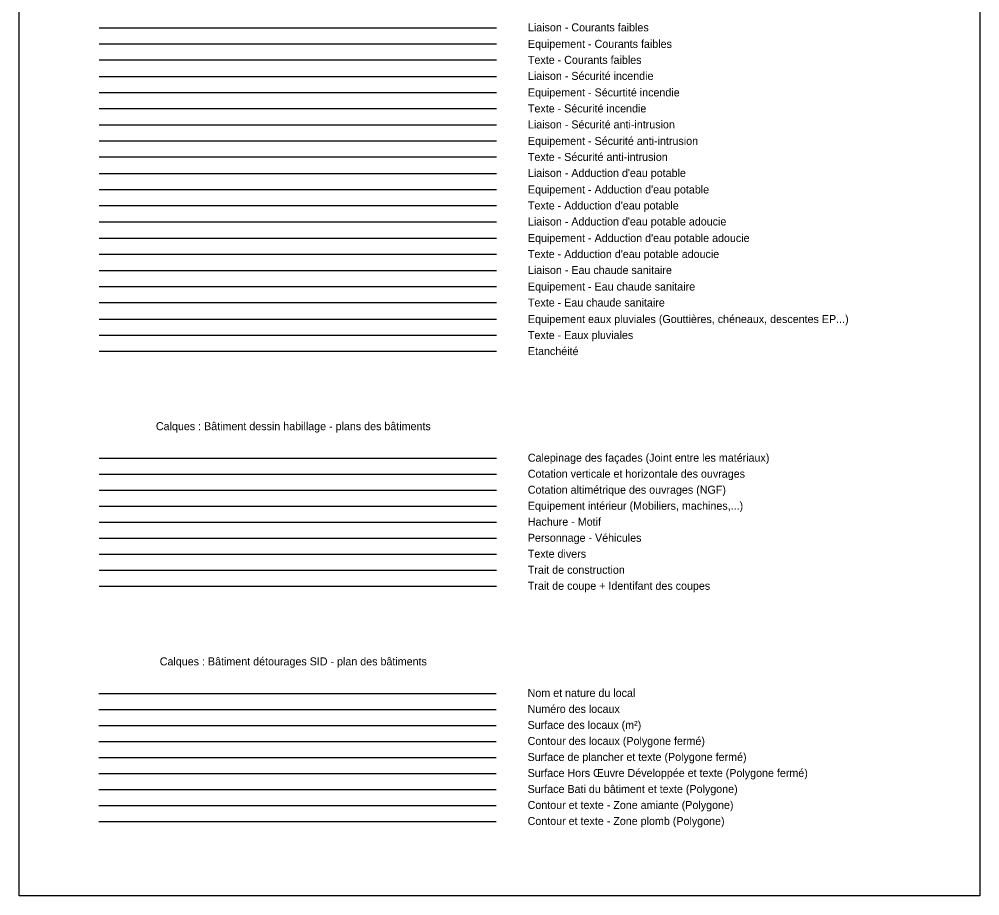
# Model space of a CAD drawing. Extents: x 703432 to 707394, y 7057985 to 7059523.
# Drawn here: x 707334.5 to 707394.5, y 7058534.6 to 7058589.3 of the extents above; entities that cross this region are included whole.
import ezdxf

# ---------------------------------------------------------------- set-up
doc = ezdxf.new("R2010")
doc.units = 0
for name, color, linetype in [('BAT_DH_CALEPINAGE_FACADE', 7, 'Continuous'), ('BAT_DH_COTATION', 7, 'Continuous'), ('BAT_DH_COTATION_NGF', 7, 'Continuous'), ('BAT_DH_EQUIP INTERIEUR', 7, 'Continuous'), ('BAT_DH_HACHURE-MOTIF', 7, 'Continuous'), ('BAT_DH_PERSONNAGE_VEHICULES', 7, 'Continuous'), ('BAT_DH_TEXTE', 7, 'Continuous'), ('BAT_DH_TRAIT CONSTRUCTION', 7, 'Continuous'), ('BAT_DH_TRAIT DE COUPE', 7, 'Continuous'), ('BAT_SID_AMIANTE_POLYLIGNE_TEXTE', 7, 'Continuous'), ('BAT_SID_LOCAL_NOM', 7, 'Continuous'), ('BAT_SID_LOCAL_NUMERO', 7, 'Continuous'), ('BAT_SID_LOCAL_POLYLIGNE', 7, 'Continuous'), ('BAT_SID_LOCAL_SURFACE', 7, 'Continuous'), ('BAT_SID_PLOMB_POLYLIGNE_TEXTE', 7, 'Continuous'), ('BAT_SID_SBAT_POLYLIGNE_TEXTE', 7, 'Continuous'), ('BAT_SID_SDP_POLYLIGNE_TEXTE', 7, 'Continuous'), ('BAT_SID_SHOD _POLYLIGNE_TEXTE', 7, 'Continuous'), ('DH_CADRE -CARTOUCHE', 7, 'Continuous'), ('GO_COUVERTURE', 7, 'Continuous'), ('SO_AEP_AD_EQUIP', 7, 'Continuous'), ('SO_AEP_AD_LIAISON', 7, 'Continuous'), ('SO_AEP_AD_TEXTE', 7, 'Continuous'), ('SO_AEP_EQUIP', 7, 'Continuous'), ('SO_AEP_LIAISON', 7, 'Continuous'), ('SO_AEP_TEXTE', 7, 'Continuous'), ('SO_ANTI_INTRUSION_EQUIP', 7, 'Continuous'), ('SO_ANTI_INTRUSION_LIAISON', 7, 'Continuous'), ('SO_ANTI_INTRUSION_TEXTE', 7, 'Continuous'), ('SO_ECS_EQUIP', 7, 'Continuous'), ('SO_ECS_LIAISON', 7, 'Continuous'), ('SO_ECS_TEXTE', 7, 'Continuous'), ('SO_ELEC_C_FAIBLES_EQUIP', 7, 'Continuous'), ('SO_ELEC_C_FAIBLES_LIAISON', 7, 'Continuous'), ('SO_ELEC_C_FAIBLES_TEXTE', 7, 'Continuous'), ('SO_EP_EQUIP', 7, 'Continuous'), ('SO_EP_TEXTE', 7, 'Continuous'), ('SO_SECU_INCENDIE_EQUIP', 7, 'Continuous'), ('SO_SECU_INCENDIE_LIAISON', 7, 'Continuous'), ('SO_SECU_INCENDIE_TEXTE', 7, 'Continuous')]:
    doc.layers.add(name, color=color, linetype=linetype)

msp = doc.modelspace()

# ---------------------------------------------------------------- linework, layer by layer
at = {"layer": 'BAT_DH_CALEPINAGE_FACADE'}
msp.add_line((707339.454, 7058561.88), (707364.274, 7058561.88), dxfattribs=at)
at = {"layer": 'BAT_DH_COTATION'}
msp.add_line((707339.454, 7058560.88), (707364.274, 7058560.88), dxfattribs=at)
at = {"layer": 'BAT_DH_COTATION_NGF'}
msp.add_line((707339.454, 7058559.88), (707364.274, 7058559.88), dxfattribs=at)
at = {"layer": 'BAT_DH_EQUIP INTERIEUR'}
msp.add_line((707339.454, 7058558.88), (707364.274, 7058558.88), dxfattribs=at)
at = {"layer": 'BAT_DH_HACHURE-MOTIF'}
msp.add_line((707339.454, 7058557.88), (707364.274, 7058557.88), dxfattribs=at)
at = {"layer": 'BAT_DH_PERSONNAGE_VEHICULES'}
msp.add_line((707339.454, 7058556.88), (707364.274, 7058556.88), dxfattribs=at)
at = {"layer": 'BAT_DH_TEXTE'}
msp.add_line((707339.454, 7058555.88), (707364.274, 7058555.88), dxfattribs=at)
at = {"layer": 'BAT_DH_TRAIT CONSTRUCTION'}
msp.add_line((707339.454, 7058554.88), (707364.274, 7058554.88), dxfattribs=at)
at = {"layer": 'BAT_DH_TRAIT DE COUPE'}
msp.add_line((707339.454, 7058553.88), (707364.274, 7058553.88), dxfattribs=at)
at = {"layer": 'BAT_SID_AMIANTE_POLYLIGNE_TEXTE'}
msp.add_line((707339.442, 7058540.19), (707364.262, 7058540.19), dxfattribs=at)
at = {"layer": 'BAT_SID_LOCAL_NOM'}
msp.add_line((707339.442, 7058547.19), (707364.262, 7058547.19), dxfattribs=at)
at = {"layer": 'BAT_SID_LOCAL_NUMERO'}
msp.add_line((707339.442, 7058546.19), (707364.262, 7058546.19), dxfattribs=at)
at = {"layer": 'BAT_SID_LOCAL_POLYLIGNE'}
msp.add_line((707339.442, 7058544.19), (707364.262, 7058544.19), dxfattribs=at)
at = {"layer": 'BAT_SID_LOCAL_SURFACE'}
msp.add_line((707339.442, 7058545.19), (707364.262, 7058545.19), dxfattribs=at)
at = {"layer": 'BAT_SID_PLOMB_POLYLIGNE_TEXTE'}
msp.add_line((707339.442, 7058539.19), (707364.262, 7058539.19), dxfattribs=at)
at = {"layer": 'BAT_SID_SBAT_POLYLIGNE_TEXTE'}
msp.add_line((707339.442, 7058541.19), (707364.262, 7058541.19), dxfattribs=at)
at = {"layer": 'BAT_SID_SDP_POLYLIGNE_TEXTE'}
msp.add_line((707339.442, 7058543.19), (707364.262, 7058543.19), dxfattribs=at)
at = {"layer": 'BAT_SID_SHOD _POLYLIGNE_TEXTE'}
msp.add_line((707339.442, 7058542.19), (707364.262, 7058542.19), dxfattribs=at)
at = {"layer": 'DH_CADRE -CARTOUCHE'}
msp.add_lwpolyline([(707334.469, 7058644.551), (707394.469, 7058644.551), (707394.469, 7058534.551), (707334.469, 7058534.551)], close=True, dxfattribs=at)
at = {"layer": 'GO_COUVERTURE'}
msp.add_line((707339.462, 7058568.57), (707364.291, 7058568.57), dxfattribs=at)
at = {"layer": 'SO_AEP_AD_EQUIP'}
msp.add_line((707339.462, 7058575.632), (707364.291, 7058575.632), dxfattribs=at)
at = {"layer": 'SO_AEP_AD_LIAISON'}
msp.add_line((707339.462, 7058576.632), (707364.276, 7058576.632), dxfattribs=at)
at = {"layer": 'SO_AEP_AD_TEXTE'}
msp.add_line((707339.462, 7058574.632), (707364.291, 7058574.632), dxfattribs=at)
at = {"layer": 'SO_AEP_EQUIP'}
msp.add_line((707339.462, 7058578.663), (707364.291, 7058578.663), dxfattribs=at)
at = {"layer": 'SO_AEP_LIAISON'}
msp.add_line((707339.462, 7058579.663), (707364.276, 7058579.663), dxfattribs=at)
at = {"layer": 'SO_AEP_TEXTE'}
msp.add_line((707339.462, 7058577.663), (707364.291, 7058577.663), dxfattribs=at)
at = {"layer": 'SO_ANTI_INTRUSION_EQUIP'}
msp.add_line((707339.462, 7058581.694), (707364.291, 7058581.694), dxfattribs=at)
at = {"layer": 'SO_ANTI_INTRUSION_LIAISON'}
msp.add_line((707339.462, 7058582.694), (707364.276, 7058582.694), dxfattribs=at)
at = {"layer": 'SO_ANTI_INTRUSION_TEXTE'}
msp.add_line((707339.462, 7058580.694), (707364.291, 7058580.694), dxfattribs=at)
at = {"layer": 'SO_ECS_EQUIP'}
msp.add_line((707339.462, 7058572.601), (707364.291, 7058572.601), dxfattribs=at)
at = {"layer": 'SO_ECS_LIAISON'}
msp.add_line((707339.462, 7058573.601), (707364.276, 7058573.601), dxfattribs=at)
at = {"layer": 'SO_ECS_TEXTE'}
msp.add_line((707339.462, 7058571.601), (707364.291, 7058571.601), dxfattribs=at)
at = {"layer": 'SO_ELEC_C_FAIBLES_EQUIP'}
msp.add_line((707339.462, 7058587.756), (707364.291, 7058587.756), dxfattribs=at)
at = {"layer": 'SO_ELEC_C_FAIBLES_LIAISON'}
msp.add_line((707339.462, 7058588.756), (707364.276, 7058588.756), dxfattribs=at)
at = {"layer": 'SO_ELEC_C_FAIBLES_TEXTE'}
msp.add_line((707339.462, 7058586.756), (707364.291, 7058586.756), dxfattribs=at)
at = {"layer": 'SO_EP_EQUIP'}
msp.add_line((707339.462, 7058570.57), (707364.291, 7058570.57), dxfattribs=at)
at = {"layer": 'SO_EP_TEXTE'}
msp.add_line((707339.462, 7058569.57), (707364.291, 7058569.57), dxfattribs=at)
at = {"layer": 'SO_SECU_INCENDIE_EQUIP'}
msp.add_line((707339.462, 7058584.725), (707364.291, 7058584.725), dxfattribs=at)
at = {"layer": 'SO_SECU_INCENDIE_LIAISON'}
msp.add_line((707339.462, 7058585.725), (707364.276, 7058585.725), dxfattribs=at)
at = {"layer": 'SO_SECU_INCENDIE_TEXTE'}
msp.add_line((707339.462, 7058583.725), (707364.291, 7058583.725), dxfattribs=at)

# ---------------------------------------------------------------- texts
at = {"layer": 'BAT_DH_CALEPINAGE_FACADE'}
msp.add_text('Calepinage des façades (Joint entre les matériaux)', height=0.5, dxfattribs=at).set_placement((707366.237, 7058561.661))
at = {"layer": 'BAT_DH_COTATION'}
msp.add_text('Cotation verticale et horizontale des ouvrages', height=0.5, dxfattribs=at).set_placement((707366.237, 7058560.661))
at = {"layer": 'BAT_DH_COTATION_NGF'}
msp.add_text('Cotation altimétrique des ouvrages (NGF)', height=0.5, dxfattribs=at).set_placement((707366.237, 7058559.661))
at = {"layer": 'BAT_DH_EQUIP INTERIEUR'}
msp.add_text('Equipement intérieur (Mobiliers, machines,...)', height=0.5, dxfattribs=at).set_placement((707366.237, 7058558.661))
at = {"layer": 'BAT_DH_HACHURE-MOTIF'}
msp.add_text('Hachure - Motif', height=0.5, dxfattribs=at).set_placement((707366.237, 7058557.661))
at = {"layer": 'BAT_DH_PERSONNAGE_VEHICULES'}
msp.add_text('Personnage - Véhicules', height=0.5, dxfattribs=at).set_placement((707366.237, 7058556.661))
at = {"layer": 'BAT_DH_TEXTE'}
msp.add_text('Texte divers', height=0.5, dxfattribs=at).set_placement((707366.237, 7058555.661))
at = {"layer": 'BAT_DH_TRAIT CONSTRUCTION'}
msp.add_text('Trait de construction', height=0.5, dxfattribs=at).set_placement((707366.237, 7058554.661))
at = {"layer": 'BAT_DH_TRAIT DE COUPE'}
msp.add_text('Trait de coupe + Identifant des coupes', height=0.5, dxfattribs=at).set_placement((707366.237, 7058553.661))
at = {"layer": 'BAT_SID_AMIANTE_POLYLIGNE_TEXTE'}
msp.add_text('Contour et texte - Zone amiante (Polygone)', height=0.5, dxfattribs=at).set_placement((707366.225, 7058539.971))
at = {"layer": 'BAT_SID_LOCAL_NOM'}
msp.add_text('Nom et nature du local', height=0.5, dxfattribs=at).set_placement((707366.225, 7058546.971))
at = {"layer": 'BAT_SID_LOCAL_NUMERO'}
msp.add_text('Numéro des locaux', height=0.5, dxfattribs=at).set_placement((707366.225, 7058545.971))
at = {"layer": 'BAT_SID_LOCAL_POLYLIGNE'}
msp.add_text('Contour des locaux (Polygone fermé)', height=0.5, dxfattribs=at).set_placement((707366.225, 7058543.971))
at = {"layer": 'BAT_SID_LOCAL_SURFACE'}
msp.add_text('Surface des locaux (m²)', height=0.5, dxfattribs=at).set_placement((707366.225, 7058544.971))
at = {"layer": 'BAT_SID_PLOMB_POLYLIGNE_TEXTE'}
msp.add_text('Contour et texte - Zone plomb (Polygone)', height=0.5, dxfattribs=at).set_placement((707366.225, 7058538.971))
at = {"layer": 'BAT_SID_SBAT_POLYLIGNE_TEXTE'}
msp.add_text('Surface Bati du bâtiment et texte (Polygone)', height=0.5, dxfattribs=at).set_placement((707366.225, 7058540.971))
at = {"layer": 'BAT_SID_SDP_POLYLIGNE_TEXTE'}
msp.add_text('Surface de plancher et texte (Polygone fermé)', height=0.5, dxfattribs=at).set_placement((707366.225, 7058542.971))
at = {"layer": 'BAT_SID_SHOD _POLYLIGNE_TEXTE'}
msp.add_text('Surface Hors Œuvre Développée et texte (Polygone fermé)', height=0.5, dxfattribs=at).set_placement((707366.225, 7058541.971))
at = {"layer": 'DH_CADRE -CARTOUCHE'}
for s, p in [(' Calques : Bâtiment dessin habillage - plans des bâtiments', (707342.821, 7058563.63)), (' Calques : Bâtiment détourages SID - plan des bâtiments', (707343.061, 7058548.94))]:
    msp.add_text(s, height=0.5, dxfattribs=at).set_placement(p)
at = {"layer": 'GO_COUVERTURE'}
msp.add_text('Etanchéité', height=0.5, dxfattribs=at).set_placement((707366.244, 7058568.32))
at = {"layer": 'SO_AEP_AD_EQUIP'}
msp.add_text("Equipement - Adduction d'eau potable adoucie", height=0.5, dxfattribs=at).set_placement((707366.244, 7058575.382))
at = {"layer": 'SO_AEP_AD_LIAISON'}
msp.add_text("Liaison - Adduction d'eau potable adoucie", height=0.5, dxfattribs=at).set_placement((707366.244, 7058576.413))
at = {"layer": 'SO_AEP_AD_TEXTE'}
msp.add_text("Texte - Adduction d'eau potable adoucie", height=0.5, dxfattribs=at).set_placement((707366.244, 7058574.382))
at = {"layer": 'SO_AEP_EQUIP'}
msp.add_text("Equipement - Adduction d'eau potable", height=0.5, dxfattribs=at).set_placement((707366.244, 7058578.413))
at = {"layer": 'SO_AEP_LIAISON'}
msp.add_text("Liaison - Adduction d'eau potable", height=0.5, dxfattribs=at).set_placement((707366.244, 7058579.444))
at = {"layer": 'SO_AEP_TEXTE'}
msp.add_text("Texte - Adduction d'eau potable", height=0.5, dxfattribs=at).set_placement((707366.244, 7058577.413))
at = {"layer": 'SO_ANTI_INTRUSION_EQUIP'}
msp.add_text('Equipement - Sécurité anti-intrusion', height=0.5, dxfattribs=at).set_placement((707366.244, 7058581.444))
at = {"layer": 'SO_ANTI_INTRUSION_LIAISON'}
msp.add_text('Liaison - Sécurité anti-intrusion', height=0.5, dxfattribs=at).set_placement((707366.244, 7058582.475))
at = {"layer": 'SO_ANTI_INTRUSION_TEXTE'}
msp.add_text('Texte - Sécurité anti-intrusion', height=0.5, dxfattribs=at).set_placement((707366.244, 7058580.444))
at = {"layer": 'SO_ECS_EQUIP'}
msp.add_text('Equipement - Eau chaude sanitaire', height=0.5, dxfattribs=at).set_placement((707366.244, 7058572.351))
at = {"layer": 'SO_ECS_LIAISON'}
msp.add_text('Liaison - Eau chaude sanitaire', height=0.5, dxfattribs=at).set_placement((707366.244, 7058573.382))
at = {"layer": 'SO_ECS_TEXTE'}
msp.add_text('Texte - Eau chaude sanitaire', height=0.5, dxfattribs=at).set_placement((707366.244, 7058571.351))
at = {"layer": 'SO_ELEC_C_FAIBLES_EQUIP'}
msp.add_text('Equipement - Courants faibles', height=0.5, dxfattribs=at).set_placement((707366.244, 7058587.506))
at = {"layer": 'SO_ELEC_C_FAIBLES_LIAISON'}
msp.add_text('Liaison - Courants faibles', height=0.5, dxfattribs=at).set_placement((707366.244, 7058588.537))
at = {"layer": 'SO_ELEC_C_FAIBLES_TEXTE'}
msp.add_text('Texte - Courants faibles', height=0.5, dxfattribs=at).set_placement((707366.244, 7058586.506))
at = {"layer": 'SO_EP_EQUIP'}
msp.add_text('Equipement eaux pluviales (Gouttières, chéneaux, descentes EP...)', height=0.5, dxfattribs=at).set_placement((707366.244, 7058570.32))
at = {"layer": 'SO_EP_TEXTE'}
msp.add_text('Texte - Eaux pluviales', height=0.5, dxfattribs=at).set_placement((707366.244, 7058569.32))
at = {"layer": 'SO_SECU_INCENDIE_EQUIP'}
msp.add_text('Equipement - Sécurtité incendie', height=0.5, dxfattribs=at).set_placement((707366.244, 7058584.475))
at = {"layer": 'SO_SECU_INCENDIE_LIAISON'}
msp.add_text('Liaison - Sécurité incendie', height=0.5, dxfattribs=at).set_placement((707366.244, 7058585.506))
at = {"layer": 'SO_SECU_INCENDIE_TEXTE'}
msp.add_text('Texte - Sécurité incendie', height=0.5, dxfattribs=at).set_placement((707366.244, 7058583.475))

doc.saveas('drawing.dxf')
